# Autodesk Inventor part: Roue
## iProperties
Created: 2002-04
Part Number: Roue
Material: Par défaut
Document SubType Name: Modélisation
Designer: Flavien MARTY
Control State: 0
Master: False
Checked Out: False
Shininess: 20.0
Length Units: 11269
Angle Units: 11279
Time Units: 11290
Mass Units: 11283
Length Display Precision: 3
Angle Display Precision: 2
Compacted: True
Density: 0.0
Volumn: 0.0
Area: 0.0
PropertySet Name: Model Information
Author: Flavien MARTY
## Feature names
1. Révolution1 [Revolution]
2. Congé1 [Fillet]
3. Réseau circulaire1 [Circular Pattern]
4. Extrusion1
